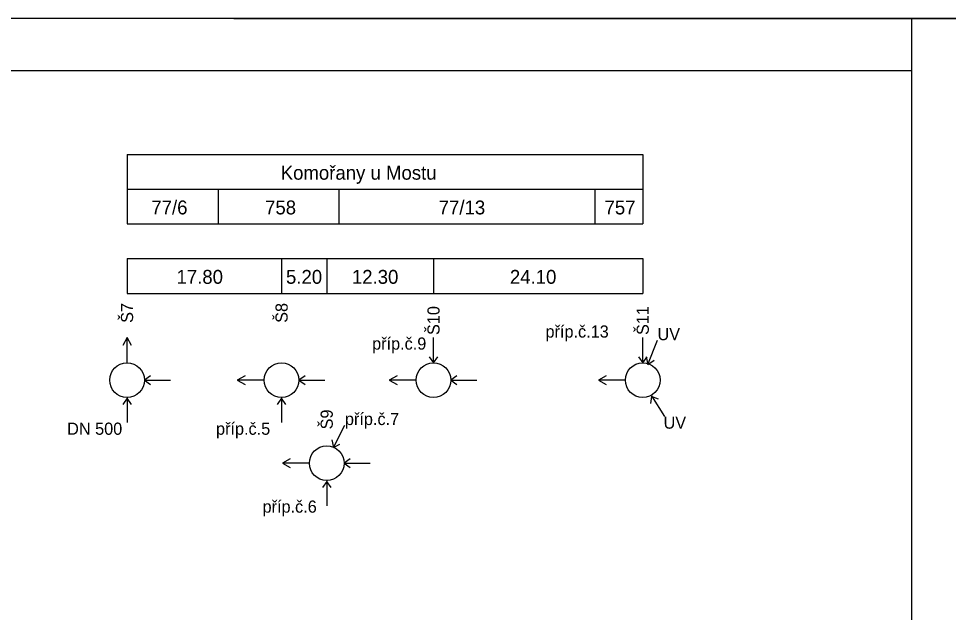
# Model space of a CAD drawing. Extents: x -760612 to 2731, y -975740 to 2995.
# Drawn here: x -398 to 673, y 2311 to 2995 of the extents above; entities that cross this region are included whole.
import ezdxf

# ---------------------------------------------------------------- set-up
doc = ezdxf.new("R2010")
doc.units = 0
for name, color, linetype in [('Border', 7, 'Continuous'), ('Implicitní', 7, 'Continuous'), ('Výřez', 7, 'Continuous')]:
    doc.layers.add(name, color=color, linetype=linetype)

# ---------------------------------------------------------------- blocks, each defined once
blk = doc.blocks.new('A3coversheet_v03_CZ_1_1')
at = {"layer": 'Border'}
blk.add_lwpolyline([(0, 0), (4.2, 0), (4.2, 2.97), (0, 2.97)], close=True, dxfattribs=at)
for points in [[(2.1, 0), (2.1, 2.97), (4.2, 2.97)], [(2.1, 0.07), (0.2, 0.07), (0.2, 2.91), (2.1, 2.91)]]:
    blk.add_lwpolyline(points, dxfattribs=at)

msp = doc.modelspace()

# ---------------------------------------------------------------- linework, layer by layer
at = {"layer": 'Implicitní'}
for p, q in [((-150, 2995), (850, 2995)), ((-273.1, 2838.3), (-273.1, 2798.3)), ((-273.1, 2838.3), (320.9, 2838.3)), ((320.9, 2838.3), (320.9, 2798.3)), ((-273.1, 2798.3), (-273.1, 2758.3)), ((-273.1, 2798.3), (-168.1, 2798.3)), ((-273.1, 2798.3), (320.9, 2798.3)), ((-168.1, 2798.3), (-168.1, 2758.3)), ((-168.1, 2798.3), (-29.1, 2798.3)), ((-29.1, 2798.3), (-29.1, 2758.3)), ((-29.1, 2798.3), (265.9, 2798.3)), ((265.9, 2798.3), (265.9, 2758.3)), ((265.9, 2798.3), (320.9, 2798.3)), ((320.9, 2798.3), (320.9, 2758.3)), ((-273.1, 2758.3), (-168.1, 2758.3)), ((-168.1, 2758.3), (-29.1, 2758.3)), ((-29.1, 2758.3), (265.9, 2758.3)), ((265.9, 2758.3), (320.9, 2758.3)), ((-273.1, 2718.3), (-273.1, 2678.3)), ((-273.1, 2718.3), (-273.1, 2718.3)), ((-273.1, 2718.3), (-273.1, 2678.3)), ((-273.1, 2718.3), (-95.1, 2718.3)), ((-95.1, 2718.3), (-95.1, 2678.3)), ((-95.1, 2718.3), (-43.1, 2718.3)), ((-43.1, 2718.3), (-43.1, 2678.3)), ((-43.1, 2718.3), (79.9, 2718.3)), ((79.9, 2718.3), (79.9, 2678.3)), ((79.9, 2718.3), (320.9, 2718.3)), ((320.9, 2718.3), (320.9, 2678.3)), ((-273.1, 2678.3), (-273.1, 2678.3)), ((-273.1, 2678.3), (-95.1, 2678.3)), ((-95.1, 2678.3), (-43.1, 2678.3)), ((-43.1, 2678.3), (79.9, 2678.3)), ((79.9, 2678.3), (320.9, 2678.3)), ((-273.1, 2627.3), (-278.1, 2618.3)), ((-273.1, 2598.3), (-273.1, 2627.3)), ((-268.1, 2618.3), (-273.1, 2627.3)), ((79.9, 2598.3), (79.9, 2627.3)), ((320.9, 2598.3), (320.9, 2627.3)), ((326.9, 2596.3), (337.9, 2624.3)), ((74.9, 2605.3), (79.9, 2598.3)), ((79.9, 2598.3), (84.9, 2605.3)), ((315.9, 2605.3), (320.9, 2598.3)), ((320.9, 2598.3), (325.9, 2605.3)), ((324.9, 2605.3), (326.9, 2596.3)), ((326.9, 2596.3), (333.9, 2601.3)), ((-246.1, 2583.3), (-253.1, 2578.3)), ((-137.1, 2583.3), (-146.1, 2578.3)), ((-68.1, 2583.3), (-75.1, 2578.3)), ((37.9, 2583.3), (28.9, 2578.3)), ((106.9, 2583.3), (99.9, 2578.3)), ((278.9, 2583.3), (269.9, 2578.3)), ((-253.1, 2578.3), (-223.1, 2578.3)), ((-253.1, 2578.3), (-246.1, 2573.3)), ((-146.1, 2578.3), (-137.1, 2573.3)), ((-115.1, 2578.3), (-145.1, 2578.3)), ((-75.1, 2578.3), (-45.1, 2578.3)), ((-75.1, 2578.3), (-68.1, 2573.3)), ((28.9, 2578.3), (37.9, 2573.3)), ((59.9, 2578.3), (29.9, 2578.3)), ((99.9, 2578.3), (129.9, 2578.3)), ((99.9, 2578.3), (106.9, 2573.3)), ((269.9, 2578.3), (278.9, 2573.3)), ((300.9, 2578.3), (270.9, 2578.3)), ((330.9, 2560.3), (345.9, 2536.3)), ((-273.1, 2557.3), (-278.1, 2550.3)), ((-273.1, 2558.3), (-273.1, 2529.3)), ((-268.1, 2550.3), (-273.1, 2557.3)), ((-95.1, 2557.3), (-100.1, 2550.3)), ((-95.1, 2558.3), (-95.1, 2529.3)), ((-90.1, 2550.3), (-95.1, 2557.3)), ((330.9, 2559.3), (329.9, 2551.3)), ((338.9, 2556.3), (330.9, 2559.3)), ((-35.1, 2500.5), (-22.1, 2526.5)), ((-37.1, 2509.5), (-35.1, 2500.5)), ((-35.1, 2500.5), (-28.1, 2504.5)), ((-85.1, 2487.5), (-94.1, 2482.5)), ((-16.1, 2487.5), (-23.1, 2482.5)), ((-94.1, 2482.5), (-85.1, 2477.5)), ((-63.1, 2482.5), (-93.1, 2482.5)), ((-23.1, 2482.5), (6.9, 2482.5)), ((-23.1, 2482.5), (-16.1, 2477.5)), ((-43.1, 2461.5), (-48.1, 2454.5)), ((-43.1, 2462.5), (-43.1, 2433.5)), ((-38.1, 2454.5), (-43.1, 2461.5))]:
    msp.add_line(p, q, dxfattribs=at)
for centre in [(-273.1, 2578.3), (-95.1, 2578.3), (79.9, 2578.3), (320.9, 2578.3), (-43.1, 2482.5)]:
    msp.add_circle(centre, 20, dxfattribs=at)
at = {"layer": 'Výřez'}
msp.add_lwpolyline([(-1469, 25), (2731, 25), (2731, 2995), (-1469, 2995)], close=True, dxfattribs=at)

# ---------------------------------------------------------------- block references
at = {"layer": 'Border', "xscale": 1000.0000004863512, "yscale": 1000.0000004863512, "rotation": 4.518606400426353e-10}
msp.add_blockref('A3coversheet_v03_CZ_1_1', (-1469, 25), dxfattribs=at)

# ---------------------------------------------------------------- texts
at = {"layer": 'Implicitní'}
for s, height, p in [('Komořany u Mostu', 16, (-96.1, 2809.3)), ('77/6', 16, (-245.1, 2769.3)), ('758', 16, (-114.1, 2769.3)), ('77/13', 16, (85.9, 2769.3)), ('757', 16, (276.9, 2769.3)), ('17.80', 16, (-216.1, 2689.3)), ('5.20', 16, (-90, 2689.3)), ('12.30', 16, (-14.1, 2689.3)), ('24.10', 16, (167.9, 2689.3)), ('příp.č.13', 14, (208.9, 2627.3)), ('UV', 14, (337.9, 2624.3)), ('příp.č.9', 14, (9.2, 2613.4)), ('příp.č.7', 14, (-22.1, 2526.5)), ('DN 500', 14, (-342.1, 2515.3)), ('příp.č.5', 14, (-170.6, 2515.3)), ('UV', 14, (344.9, 2522.3)), ('příp.č.6', 14, (-117, 2425.5))]:
    msp.add_text(s, height=height, dxfattribs=at).set_placement(p)
for s, p in [('Š7', (-266.1, 2644.3)), ('Š8', (-88.1, 2644.3)), ('Š10', (86.9, 2630.3)), ('Š11', (327.9, 2630.3)), ('Š9', (-36.1, 2521.5))]:
    msp.add_text(s, height=14, rotation=90, dxfattribs=at).set_placement(p)

doc.saveas('drawing.dxf')
